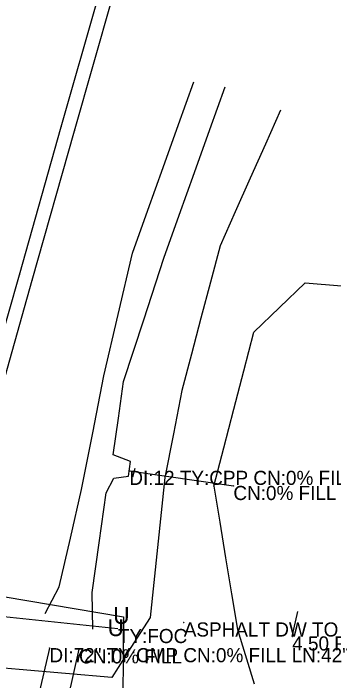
# Model space of a CAD drawing. Extents: x 929765 to 934279, y 1533086 to 1541189.
# Drawn here: x 932097.7 to 932210.9, y 1537538.1 to 1537774.2 of the extents above; entities that cross this region are included whole.
import ezdxf

# ---------------------------------------------------------------- set-up
doc = ezdxf.new("R2010")
doc.units = 0
for name, color, linetype in [('Default', 7, 'Continuous'), ('S_CROSS_DRAIN', 7, 'Continuous'), ('S_CROSS_DRAIN_ANNOT', 7, 'Continuous'), ('S_DITCHLINE', 7, 'Continuous'), ('S_DRG_PT_SYM', 7, 'Continuous'), ('S_DRIVEWAY', 7, 'Continuous'), ('S_EDGE_PAVEMENT', 7, 'Continuous'), ('S_HEADWALL', 7, 'Continuous'), ('S_MSC_PT_SYM', 7, 'Continuous'), ('S_RAILROAD', 7, 'Continuous'), ('S_SIGN', 7, 'Continuous'), ('S_SIGN_ANNOT', 7, 'Continuous'), ('S_SURVEY_TEXT_ANNOT', 7, 'Continuous'), ('S_UNDERGROUND_CABLE', 7, 'Continuous'), ('S_UNDERGROUND_CABLE_ANNOT', 7, 'Continuous')]:
    doc.layers.add(name, color=color, linetype=linetype)

msp = doc.modelspace()

# ---------------------------------------------------------------- linework, layer by layer
at = {"layer": 'S_CROSS_DRAIN'}
for p, q in [((932138.66, 1537612.32), (932175.44, 1537606.97)), ((932110.43, 1537549.57), (932101.07, 1537509)), ((932111.82, 1537508.52), (932120.89, 1537549.16))]:
    msp.add_line(p, q, dxfattribs=at)
at = {"layer": 'S_DITCHLINE'}
for points in [[(932108.88, 1537561.79), (932113.89, 1537571.29), (932117.84, 1537588.49), (932121.78, 1537605.68), (932125.7, 1537625.79), (932129.62, 1537645.9), (932134.68, 1537667.63), (932139.74, 1537689.36), (932145.18, 1537704.52), (932150.62, 1537719.68), (932156.05, 1537734.84), (932161.49, 1537750)], [(932125.8, 1537556.23), (932125.57, 1537569.26), (932128.02, 1537586.87), (932130.47, 1537604.49), (932133.18, 1537609.73), (932138.35, 1537610.42), (932139.1, 1537615.67), (932132.99, 1537618.01), (932134.79, 1537630.94), (932136.59, 1537643.87), (932143.73, 1537665.72), (932150.87, 1537687.56), (932156.29, 1537702.73), (932161.72, 1537717.9), (932167.14, 1537733.07), (932172.56, 1537748.24)]]:
    msp.add_lwpolyline(points, dxfattribs=at)
at = {"layer": 'S_DRG_PT_SYM'}
for points in [[(932138.66, 1537612.32), (932138.66, 1537612.37), (932138.66, 1537612.32), (932138.61, 1537612.32), (932138.66, 1537612.32), (932138.66, 1537612.27), (932138.66, 1537612.32), (932138.71, 1537612.32)], [(932175.44, 1537606.97), (932175.44, 1537607.02), (932175.44, 1537606.97), (932175.39, 1537606.97), (932175.44, 1537606.97), (932175.44, 1537606.92), (932175.44, 1537606.97), (932175.49, 1537606.97)], [(932110.43, 1537549.57), (932110.43, 1537549.62), (932110.43, 1537549.57), (932110.38, 1537549.57), (932110.43, 1537549.57), (932110.43, 1537549.52), (932110.43, 1537549.57), (932110.48, 1537549.57)], [(932120.89, 1537549.16), (932120.89, 1537549.21), (932120.89, 1537549.16), (932120.84, 1537549.16), (932120.89, 1537549.16), (932120.89, 1537549.11), (932120.89, 1537549.16), (932120.94, 1537549.16)]]:
    msp.add_lwpolyline(points, dxfattribs=at)
at = {"layer": 'S_DRIVEWAY'}
for points in [[(932192.08, 1537739.9), (932186.74, 1537727.9), (932181.41, 1537715.91), (932176.08, 1537703.91), (932170.74, 1537691.92), (932167.36, 1537679.13), (932163.97, 1537666.35), (932160.59, 1537653.56), (932157.21, 1537640.78), (932154.21, 1537625.39), (932151.22, 1537610)], [(932168.54, 1537606.85), (932172.06, 1537620.48), (932175.58, 1537634.11), (932179.11, 1537647.74), (932182.63, 1537661.37), (932191.72, 1537670.1), (932200.81, 1537678.82), (932213.61, 1537677.72), (932226.42, 1537676.61), (932239.22, 1537675.51), (932252.02, 1537674.4)], [(932151.22, 1537610), (932148.6, 1537585.2), (932145.99, 1537560.39)], [(932168.54, 1537606.85), (932170.62, 1537594.18), (932172.7, 1537581.5), (932174.79, 1537568.83), (932176.87, 1537556.16)], [(932145.99, 1537560.39), (932139.22, 1537549.76), (932132.45, 1537539.14)], [(932176.87, 1537556.16), (932182.78, 1537536.97)]]:
    msp.add_lwpolyline(points, dxfattribs=at)
at = {"layer": 'S_EDGE_PAVEMENT'}
msp.add_lwpolyline([(932132.45, 1537539.14), (932116.07, 1537540.56), (932099.7, 1537541.99), (932083.32, 1537543.41), (932066.94, 1537544.83)], dxfattribs=at)
at = {"layer": 'S_HEADWALL'}
msp.add_lwpolyline([(932139.84, 1537610.22), (932140.74, 1537613.28)], dxfattribs=at)
at = {"layer": 'S_MSC_PT_SYM'}
for points in [[(932114.55, 1537734.1), (932114.55, 1537734.15), (932114.55, 1537734.1), (932114.5, 1537734.1), (932114.55, 1537734.1), (932114.55, 1537734.05), (932114.55, 1537734.1), (932114.6, 1537734.1)], [(932119.29, 1537732.65), (932119.29, 1537732.7), (932119.29, 1537732.65), (932119.24, 1537732.65), (932119.29, 1537732.65), (932119.29, 1537732.59), (932119.29, 1537732.65), (932119.34, 1537732.65)], [(932099.81, 1537681.72), (932099.81, 1537681.77), (932099.81, 1537681.72), (932099.76, 1537681.72), (932099.81, 1537681.72), (932099.81, 1537681.67), (932099.81, 1537681.72), (932099.86, 1537681.72)], [(932104.37, 1537679.83), (932104.37, 1537679.88), (932104.37, 1537679.83), (932104.32, 1537679.83), (932104.37, 1537679.83), (932104.37, 1537679.78), (932104.37, 1537679.83), (932104.42, 1537679.83)], [(932198.22, 1537562.53), (932198.22, 1537562.58), (932198.22, 1537562.53), (932198.17, 1537562.53), (932198.22, 1537562.53), (932198.22, 1537562.48), (932198.22, 1537562.53), (932198.27, 1537562.53)], [(932157.91, 1537558.67), (932157.91, 1537558.72), (932157.91, 1537558.67), (932157.86, 1537558.67), (932157.91, 1537558.67), (932157.91, 1537558.62), (932157.91, 1537558.67), (932157.96, 1537558.67)], [(932196.22, 1537553.73), (932196.22, 1537553.78), (932196.22, 1537553.73), (932196.17, 1537553.73), (932196.22, 1537553.73), (932196.22, 1537553.68), (932196.22, 1537553.73), (932196.27, 1537553.73)]]:
    msp.add_lwpolyline(points, dxfattribs=at)
at = {"layer": 'S_RAILROAD'}
for p, q in [((932114.55, 1537734.1), (932129.95, 1537788.14)), ((932119.29, 1537732.65), (932134.58, 1537786.4)), ((932099.81, 1537681.72), (932114.55, 1537734.1)), ((932104.37, 1537679.83), (932119.29, 1537732.65)), ((932084.46, 1537627.73), (932099.81, 1537681.72)), ((932089.34, 1537626.62), (932104.37, 1537679.83))]:
    msp.add_line(p, q, dxfattribs=at)
at = {"layer": 'S_SIGN'}
msp.add_line((932196.22, 1537553.73), (932198.22, 1537562.53), dxfattribs=at)
at = {"layer": 'S_UNDERGROUND_CABLE'}
for p, q in [((932134.61, 1537556.35), (932047.91, 1537565.6)), ((932094.03, 1537567.82), (932136.59, 1537560.67)), ((932136.59, 1537560.67), (932135.91, 1537489.36))]:
    msp.add_line(p, q, dxfattribs=at)

# ---------------------------------------------------------------- texts
at = {"layer": 'Default'}
for p in [(932132.96, 1537558.12), (932130.98, 1537553.81)]:
    msp.add_text('U', height=6, rotation=360, dxfattribs=at).set_placement(p)
at = {"layer": 'S_CROSS_DRAIN_ANNOT'}
for s, p in [("DI:12 TY:CPP CN:0% FILL LN:38'", (932138.66, 1537607.32)), ('CN:0% FILL', (932175.44, 1537601.97)), ('DI:72" TY:CMP CN:0% FILL LN:42\'', (932110.43, 1537544.57)), ('CN:0% FILL', (932120.89, 1537544.16))]:
    msp.add_text(s, height=5, dxfattribs=at).set_placement(p)
at = {"layer": 'S_SIGN_ANNOT'}
msp.add_text('4.50 FARMERSMARKET NA TY:MPL', height=5, dxfattribs=at).set_placement((932196.22, 1537548.73))
at = {"layer": 'S_SURVEY_TEXT_ANNOT'}
msp.add_text('ASPHALT DW TO MARKET', height=5, dxfattribs=at).set_placement((932157.91, 1537553.67))
at = {"layer": 'S_UNDERGROUND_CABLE_ANNOT'}
msp.add_text('TY:FOC', height=5, dxfattribs=at).set_placement((932134.61, 1537551.35))

doc.saveas('drawing.dxf')
